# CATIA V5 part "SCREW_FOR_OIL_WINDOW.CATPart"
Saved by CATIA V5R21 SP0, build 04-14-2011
Part number: EN ISO 4762 SCREW M5x16 STEEL HEXAGON SOCKET HEAD CAP
Publications: "Mating Face", "Axis"
Bounding box of the stored display mesh (mm): x -18 to 4, y -4.5 to 4.5, z -4.5 to 4.5
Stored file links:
  C:\Users\MIRCEA\Desktop\MOM\Mogan\model\SCREW_FOR_OIL_WINDOW.CATPart
  C:\Program Files (x86)\Dassault Systemes\B21\intel_a\startup\components\MechanicalStandardParts\EN_Standards\Design_Tables\EN_ISO_4762_HEXAGON_SOCKET_HEAD_CAP_SCREW.txt
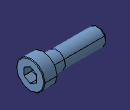
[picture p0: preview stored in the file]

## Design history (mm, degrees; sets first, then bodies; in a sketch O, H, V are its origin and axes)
Parameters
  d_dia = 5.5 mm
  l_nom = 18 mm
  k_head_depth_max = 4 mm
  s_nom = 4 mm
  r_min = 0.2 mm
  ds_max = 5.5 mm
  e = 4.583 mm
  t_min = 2.5 mm
  p_pitch = 0.8 mm
  Threading = 13.6 mm
  dk_max = 9 mm
Body1 "PartBody" (main body)
  Sketch1 on yz-plane, origin (0, 0, 0), H (0, 1, 0), V (0, 0, 1)
    circle A1 centre (0, 0) radius 4.5
    radius A1 = 4.5 {= dk_max /2}
  Pad1: profile Sketch1, direction (1, 0, 0), length 4 {= k_head_depth_max}
  Fillet1: radius 0.2 {= r_min}, on edge [face of Pad1 | face of Pad1]
  Body2
    Sketch2 on face of Pad1, origin (4, 0, 0), H (0, 1, 0), V (0, 0, 1)
      point P1 (2, -1.1547)
      point P2 (2, 1.1547)
      point P3 (0, 2.3094)
      point P4 (-2, 1.1547)
      point P5 (-2, -1.1547)
      point P6 (0, -2.3094)
      point P7 (2, 0)
      line L1 (2, -1.1547) -> (2, 1.1547)
      line L2 (2, 1.1547) -> (0, 2.3094)
      line L3 (0, 2.3094) -> (-2, 1.1547)
      line L4 (-2, 1.1547) -> (-2, -1.1547)
      line L5 (-2, -1.1547) -> (0, -2.3094)
      line L6 (0, -2.3094) -> (2, -1.1547)
      construction line L7 (0, 0) -> (2, 0)
      construction circle A1 centre (0, 0) radius 2.3094
      construction arc A2 centre (-2, -1.1547) radius 2.3094 from (-2, 1.1547) to (0, -2.3094) cw
      construction arc A3 centre (2, 1.1547) radius 2.3094 from (0, 2.3094) to (2, -1.1547) ccw
      point P8 (-2, -1.1547)
      point P9 (2, 1.1547)
      distance L1 L4 = 4 {= s_nom}
      horizontal: L7 H
      coincidence: A1 P1, A1 P2, A1 P3, A1 P4, A1 P5, A1 P6, A2 P4, A2 P6, A2 O, P8 P5, A3 P3, A3 P1, A3 O, P9 P2
      midpoint: P7 L1
    Pad2: profile Sketch2, direction (-1, 0, 0), length 3.8207 {= t_min +(e /3.47)}
    Body3
      Sketch3 on zx-plane, origin (0, 0, 0), H (-1, 0, 0), V (0, 0, 1)
        point P1 (-0.177, 0)
        line L1 (-0.177, 0) -> (-1.5, 2.2915)
        line L2 (-1.5, 2.2915) -> (-4, 2.2915)
        line L3 (-4, 2.2915) -> (-4, 0)
        axis line L4 (-46.2384, 0) -> (26.3409, 0)
        reference projected line E1 (-4, -6.9227) -> (-4, 6.9227) from edge [face of Pad2 | face of Pad2]
        length L2 = 2.5 {= t_min}
        angle L1 L4 = 60
        distance L2 L4 = 2.2915 {= e /2}
        horizontal: L2 H, L4 H
        perpendicularity: L3 L2
        fix: L4
        coincidence: L3 E1, P1 L4
      Shaft1: profile Sketch3, axis Sketch3.L4, angle 360
    Intersect1: tool Body3
  Remove1: tool Body2
  Sketch4 on xy-plane, origin (0, 0, 0), H (1, 0, 0), V (0, 1, 0)
    line L1 (0, 0) -> (0, 2.75)
    line L2 (0, 2.75) -> (-4.4, 2.75)
    line L3 (-4.4, 2.75) -> (-4.4, 2.6829)
    line L4 (-4.4, 2.6829) -> (-18, 2.6829)
    line L5 (-18, 2.6829) -> (-18, 0)
    axis line L6 (-192.3446, 0) -> (99.1594, 0)
    distance L5 L1 = 18 {= l_nom}
    distance L3 L5 = 13.6 {= Threading}
    distance L2 L6 = 2.75 {= ds_max /2}
    distance L4 L6 = 2.6829 {= d_dia /2.05}
    vertical: L1 V, L3 V, L5 V
    horizontal: L2 H, L4 H, L6 H
    fix: L6
  Shaft2: profile Sketch4, axis Sketch4.L6, angle 360
  Fillet2: radius 0.2 {= r_min}, on edge [face of Shaft2 | face of Pad1]
  Chamfer1: length 0.8 {= p_pitch}, angle 45, on edge [face of Shaft2 | face of Shaft2]
  Thread1: diameter 5.3659 {= d_dia /1.025}, depth 13.6 {= Threading}, pitch 1, on face of Shaft2, from face of Shaft2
